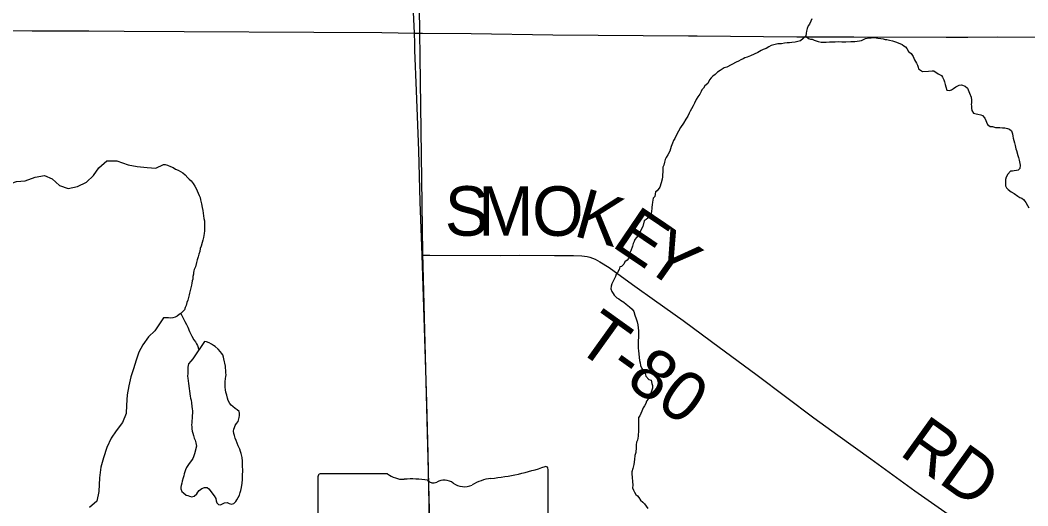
# Model space of a CAD drawing. Extents: x 0 to 34, y 0 to 22.
# Drawn here: x 6.525 to 7.68, y 16.8 to 17.358 of the extents above; entities that cross this region are included whole.
import ezdxf

# ---------------------------------------------------------------- set-up
doc = ezdxf.new("R2010")
doc.units = 0
for name, color, linetype in [('GM_X_County_Road', 7, 'Continuous'), ('GM_X_Minor_Lake', 7, 'Continuous'), ('GM_X_Minor_River', 7, 'Continuous'), ('GM_X_Rail_Line', 7, 'Continuous'), ('GM_X_State_Route', 7, 'Continuous'), ('GM_X_State_Shield', 7, 'Continuous'), ('GM_X_Township_Road', 7, 'Continuous'), ('GM_X_Township_Road_Text', 7, 'Continuous')]:
    doc.layers.add(name, color=color, linetype=linetype)

msp = doc.modelspace()

# ---------------------------------------------------------------- linework, layer by layer
at = {"layer": 'GM_X_County_Road'}
for points in [[(6.1692, 17.3475), (6.2373, 17.3474), (6.3118, 17.3469), (6.3927, 17.3464), (6.5388, 17.3456), (6.604, 17.3453), (6.6444, 17.3451), (6.7129, 17.3447), (6.8618, 17.3438), (6.9395, 17.3434), (6.9768, 17.3429)], [(6.9768, 17.3429), (6.9861, 17.3428), (7.0421, 17.3422), (7.1354, 17.3407), (7.2908, 17.3398), (7.3009, 17.3397)], [(7.3009, 17.3397), (7.4151, 17.3387), (7.4804, 17.3384), (7.586, 17.338), (7.6111, 17.3382)], [(7.6111, 17.3382), (7.6451, 17.3384), (7.7944, 17.3378), (7.8503, 17.3373), (7.8877, 17.3371), (7.9343, 17.3368), (8.0462, 17.3362), (8.1332, 17.3351), (8.163, 17.335)]]:
    msp.add_lwpolyline(points, dxfattribs=at)
at = {"layer": 'GM_X_Minor_Lake'}
for points in [[(6.7365, 16.9889), (6.723, 16.969), (6.7208, 16.9663), (6.7181, 16.9633), (6.7174, 16.9594), (6.7171, 16.9568), (6.7171, 16.9545), (6.7171, 16.9522), (6.7168, 16.9492), (6.7172, 16.9469), (6.7176, 16.9438), (6.718, 16.9408), (6.7201, 16.9263)], [(6.7714, 16.8782), (6.7707, 16.8812), (6.7699, 16.8835), (6.7695, 16.8862), (6.7698, 16.8885), (6.7706, 16.8904), (6.7717, 16.8927), (6.7732, 16.895), (6.7751, 16.8973), (6.7761, 16.9018), (6.7765, 16.9041), (6.7765, 16.9068), (6.7761, 16.9087), (6.7738, 16.9106), (6.7715, 16.9121), (6.7688, 16.9143), (6.7669, 16.9158), (6.7653, 16.9177), (6.7634, 16.9215), (6.7626, 16.9241), (6.7618, 16.9276), (6.761, 16.931), (6.7606, 16.9336), (6.7602, 16.9367), (6.7602, 16.9386), (6.7602, 16.9409), (6.7602, 16.9428), (6.7605, 16.9466), (6.7608, 16.9489), (6.7612, 16.9508), (6.7608, 16.953), (6.7608, 16.9561), (6.7604, 16.9584), (6.7604, 16.9607), (6.7584, 16.969), (6.758, 16.9709), (6.7572, 16.9736), (6.756, 16.9755), (6.7549, 16.9773), (6.7522, 16.9804), (6.7487, 16.9834), (6.7468, 16.9845), (6.7445, 16.986), (6.7418, 16.9875), (6.7388, 16.9886), (6.7365, 16.9889)], [(6.7201, 16.9263), (6.7204, 16.9241), (6.7212, 16.9218), (6.7216, 16.9188), (6.722, 16.9146), (6.7224, 16.9119), (6.7225, 16.9093), (6.7225, 16.9066), (6.7221, 16.9043), (6.7222, 16.9013), (6.7218, 16.8978), (6.7219, 16.8956), (6.7215, 16.8933), (6.7219, 16.891), (6.7219, 16.8887), (6.7223, 16.8861), (6.7231, 16.8838), (6.7239, 16.8811), (6.7247, 16.8781), (6.7258, 16.8758), (6.7266, 16.8728), (6.727, 16.8709), (6.7271, 16.869), (6.7249, 16.8602), (6.7238, 16.8568), (6.723, 16.8549), (6.7215, 16.8526), (6.7189, 16.8491), (6.7174, 16.8468), (6.7159, 16.8445), (6.7148, 16.8418), (6.7137, 16.8395), (6.7129, 16.8372), (6.7126, 16.835), (6.7118, 16.8327), (6.7107, 16.8289), (6.7104, 16.8266), (6.7096, 16.8239), (6.7093, 16.822), (6.7093, 16.8201), (6.7105, 16.8171), (6.7124, 16.8152), (6.7155, 16.8129), (6.7174, 16.8122), (6.7193, 16.8114), (6.7219, 16.8107), (6.7246, 16.8115), (6.7276, 16.8142), (6.7287, 16.8161), (6.7302, 16.818), (6.7332, 16.8203), (6.7363, 16.8215), (6.7393, 16.8215), (6.7412, 16.82), (6.7474, 16.8121), (6.7493, 16.8087), (6.7497, 16.8064), (6.7505, 16.8038), (6.7524, 16.8019), (6.7547, 16.8015), (6.757, 16.8027), (6.7593, 16.8039), (6.7623, 16.8043), (6.7646, 16.8032), (6.7673, 16.8024), (6.7699, 16.8032), (6.7722, 16.8055), (6.7733, 16.8074), (6.7748, 16.8101), (6.7763, 16.8128), (6.7774, 16.8158), (6.7781, 16.8181), (6.7789, 16.8216), (6.7796, 16.8265), (6.7799, 16.8307), (6.7799, 16.8353), (6.7802, 16.841), (6.7801, 16.8463), (6.7801, 16.8516), (6.7797, 16.8558), (6.7785, 16.8604), (6.7777, 16.863), (6.7769, 16.8653), (6.7757, 16.8676), (6.7749, 16.8695), (6.7726, 16.8755), (6.7714, 16.8782)]]:
    msp.add_lwpolyline(points, dxfattribs=at)
at = {"layer": 'GM_X_Minor_River'}
for points in [[(7.4322, 17.3593), (7.4311, 17.3566), (7.4296, 17.3531), (7.4281, 17.3512), (7.427, 17.3482), (7.4263, 17.3451), (7.4256, 17.3428), (7.4252, 17.3394), (7.4192, 17.334), (7.4131, 17.3324), (7.4093, 17.332), (7.4067, 17.3316), (7.404, 17.3316), (7.401, 17.3312), (7.3976, 17.3307), (7.3934, 17.3307), (7.3888, 17.3295), (7.3858, 17.3287), (7.3831, 17.3272), (7.3801, 17.3252), (7.3763, 17.324), (7.3741, 17.3229), (7.3703, 17.3206), (7.3661, 17.3186), (7.362, 17.3167), (7.3582, 17.3151), (7.3555, 17.3143), (7.3536, 17.3132), (7.351, 17.312), (7.3483, 17.3108), (7.3457, 17.3093), (7.3347, 17.3038), (7.3317, 17.303), (7.3294, 17.3015), (7.3272, 17.2999), (7.3241, 17.298), (7.3215, 17.2953), (7.3189, 17.2934), (7.317, 17.2915), (7.3151, 17.2892), (7.3129, 17.285), (7.3098, 17.2823), (7.308, 17.2796), (7.3061, 17.2776), (7.3054, 17.2757), (7.3039, 17.2727), (7.3016, 17.2696), (7.2997, 17.2665), (7.2979, 17.2623), (7.2964, 17.2593), (7.2945, 17.2558), (7.2927, 17.2532), (7.2915, 17.2509), (7.29, 17.2474), (7.2878, 17.244), (7.2852, 17.2394), (7.2818, 17.2344), (7.2796, 17.2302), (7.2773, 17.226), (7.2751, 17.2221), (7.2736, 17.2195), (7.2725, 17.2164), (7.271, 17.2126), (7.2695, 17.2072), (7.2673, 17.203), (7.2654, 17.2), (7.2643, 17.1977), (7.2636, 17.1946), (7.2625, 17.1912), (7.2617, 17.1889), (7.2614, 17.1866), (7.2614, 17.1832), (7.2611, 17.1805), (7.2611, 17.1779), (7.2607, 17.1752), (7.2596, 17.171), (7.2582, 17.166), (7.2552, 17.1618), (7.2533, 17.1607), (7.2522, 17.1553), (7.2503, 17.1534), (7.2496, 17.1488), (7.2493, 17.1458), (7.2489, 17.1431), (7.2489, 17.1412), (7.2486, 17.1389), (7.2482, 17.1351), (7.2464, 17.132), (7.2426, 17.129), (7.2403, 17.1274), (7.2385, 17.1209), (7.2362, 17.1167)], [(7.4252, 17.3394), (7.4283, 17.3368), (7.4306, 17.336), (7.4325, 17.3357), (7.4348, 17.3346), (7.4393, 17.3331), (7.4428, 17.3324), (7.4451, 17.3324), (7.4485, 17.3324), (7.4523, 17.3328), (7.4553, 17.3329), (7.4591, 17.3329), (7.4629, 17.3333), (7.4667, 17.333), (7.4713, 17.333), (7.477, 17.3331), (7.4815, 17.3331), (7.4842, 17.3336), (7.4869, 17.334), (7.4891, 17.3344), (7.4937, 17.3367), (7.4978, 17.3375), (7.5001, 17.3375), (7.5035, 17.3376), (7.5077, 17.3372), (7.5112, 17.3365), (7.5138, 17.3361), (7.5161, 17.3354), (7.518, 17.3354), (7.5214, 17.3347), (7.5245, 17.334), (7.5268, 17.3332), (7.5291, 17.3325), (7.5356, 17.3299), (7.5375, 17.3284), (7.5394, 17.3269), (7.5409, 17.325), (7.5429, 17.3216), (7.5459, 17.3194), (7.5482, 17.316), (7.5498, 17.3122), (7.5521, 17.3084), (7.5533, 17.3061), (7.5541, 17.3038), (7.5545, 17.3019), (7.5591, 17.2986), (7.5659, 17.299), (7.5701, 17.2994), (7.572, 17.2995), (7.5769, 17.2961), (7.5808, 17.2942), (7.5819, 17.2923), (7.5835, 17.2893), (7.5843, 17.287), (7.5851, 17.284), (7.5858, 17.281), (7.587, 17.2775), (7.5901, 17.2768), (7.5923, 17.2776), (7.5946, 17.2791), (7.5972, 17.2811), (7.601, 17.283), (7.6037, 17.2834), (7.6079, 17.282), (7.6106, 17.2797), (7.6129, 17.274), (7.6148, 17.2695), (7.6153, 17.2657), (7.6153, 17.263), (7.6149, 17.2611), (7.615, 17.2592), (7.615, 17.2569), (7.6154, 17.2539), (7.6173, 17.2508), (7.6204, 17.2501), (7.6226, 17.2498), (7.6257, 17.249), (7.6276, 17.2483), (7.6303, 17.2453), (7.6334, 17.2381), (7.6365, 17.2358), (7.6391, 17.2355), (7.6426, 17.2347), (7.6452, 17.2344), (7.6475, 17.2344), (7.6506, 17.2341), (7.6532, 17.2341), (7.6563, 17.2334), (7.6586, 17.2326), (7.6609, 17.2308), (7.662, 17.2273), (7.6624, 17.2247), (7.6628, 17.2224), (7.6636, 17.2197), (7.6644, 17.2171), (7.6652, 17.2137), (7.666, 17.2099), (7.6668, 17.208), (7.6684, 17.2023), (7.6691, 17.2), (7.6696, 17.197)], [(6.4874, 17.1877), (6.4887, 17.1752), (6.4964, 17.1688), (6.5093, 17.1685), (6.521, 17.1727), (6.5309, 17.1732), (6.5423, 17.1774), (6.5529, 17.1794), (6.5617, 17.1757), (6.5701, 17.1681), (6.58, 17.1644), (6.591, 17.1667), (6.6012, 17.1717), (6.6091, 17.1794), (6.6155, 17.1882), (6.6246, 17.1962), (6.636, 17.1963), (6.6489, 17.1918), (6.6592, 17.1896), (6.6706, 17.1885), (6.6805, 17.1878), (6.6894, 17.1921)], [(6.6894, 17.1921), (6.6915, 17.1921), (6.6938, 17.1913), (6.6976, 17.1898), (6.7003, 17.1887), (6.703, 17.1869), (6.7064, 17.1854), (6.7087, 17.1839), (6.7114, 17.1824), (6.7144, 17.1801), (6.7171, 17.1767), (6.719, 17.1752), (6.721, 17.1733), (6.7233, 17.1703), (6.7252, 17.1673), (6.7268, 17.1646), (6.7303, 17.1567), (6.7314, 17.1544), (6.7318, 17.1514), (6.733, 17.1468), (6.7338, 17.1427), (6.7346, 17.1392), (6.735, 17.1362), (6.7354, 17.1332), (6.7358, 17.1301), (6.7363, 17.1275), (6.7363, 17.1248), (6.7363, 17.1218), (6.7363, 17.1191), (6.7364, 17.116), (6.736, 17.113), (6.7353, 17.1084), (6.7346, 17.1054), (6.7338, 17.1027), (6.7324, 17.0985), (6.7316, 17.0958), (6.7309, 17.0924), (6.7298, 17.0893), (6.7291, 17.0863), (6.728, 17.0828), (6.7272, 17.0798), (6.7261, 17.0748), (6.7246, 17.0718), (6.7243, 17.0699), (6.7239, 17.068), (6.7236, 17.0661), (6.7232, 17.0634), (6.7229, 17.0607), (6.7221, 17.0588), (6.7218, 17.0561), (6.7214, 17.0535), (6.7207, 17.0504), (6.7199, 17.0474), (6.7192, 17.0443), (6.7189, 17.0424), (6.7181, 17.0394), (6.7174, 17.0363), (6.7163, 17.0336), (6.7152, 17.0302), (6.7144, 17.0279), (6.7133, 17.0252), (6.7111, 17.0229), (6.7092, 17.021), (6.7073, 17.0198), (6.705, 17.0179), (6.7028, 17.0168), (6.7001, 17.016), (6.6975, 17.0156), (6.6952, 17.0163), (6.6914, 17.0163), (6.6894, 17.0162), (6.6894, 17.0162), (6.6898, 17.0162)], [(7.6696, 17.197), (7.67, 17.1951), (7.6704, 17.1932), (7.6708, 17.1913), (7.6704, 17.1875), (7.6685, 17.1855), (7.6666, 17.1851), (7.664, 17.1847), (7.6621, 17.1843), (7.6598, 17.1843), (7.6568, 17.1809), (7.6549, 17.1774), (7.6542, 17.1747), (7.6542, 17.1725), (7.6542, 17.1698), (7.6543, 17.1675), (7.6554, 17.1652), (7.6573, 17.1634), (7.6608, 17.1607), (7.6639, 17.1589), (7.6681, 17.1559), (7.6707, 17.1544), (7.6727, 17.1536), (7.6746, 17.1521), (7.6761, 17.1502), (7.6776, 17.1484), (7.6792, 17.1449), (7.6807, 17.1423)], [(7.2362, 17.1167), (7.234, 17.1117), (7.2314, 17.1083), (7.2295, 17.106), (7.2288, 17.1037), (7.2277, 17.1014), (7.2269, 17.0984), (7.2247, 17.093), (7.2236, 17.0907), (7.2229, 17.0869), (7.2221, 17.0842), (7.2206, 17.0823), (7.218, 17.0804), (7.2169, 17.0777), (7.2142, 17.075), (7.2123, 17.0746), (7.2116, 17.0716), (7.2097, 17.0681), (7.2079, 17.0662), (7.2071, 17.0635), (7.2056, 17.0605), (7.2041, 17.0574), (7.203, 17.0551), (7.2023, 17.0524), (7.2019, 17.0494), (7.2031, 17.0463), (7.2047, 17.0441), (7.2058, 17.0422), (7.2089, 17.0392), (7.2112, 17.0381), (7.2131, 17.0366), (7.215, 17.0354), (7.2169, 17.0343), (7.2196, 17.0317), (7.2234, 17.0287), (7.2265, 17.026), (7.2284, 17.0234), (7.2296, 17.0192), (7.2308, 17.0151), (7.232, 17.0116), (7.2328, 17.0082), (7.2332, 17.0048), (7.2336, 17.0014), (7.2336, 16.998), (7.2337, 16.9957), (7.2337, 16.9934), (7.2333, 16.9907), (7.2333, 16.9884), (7.2334, 16.9843), (7.2334, 16.9812), (7.2338, 16.9782), (7.2339, 16.9747), (7.2343, 16.9706), (7.2347, 16.9671), (7.2355, 16.9645), (7.2359, 16.9615), (7.2375, 16.958), (7.2413, 16.9524), (7.2421, 16.9493), (7.2456, 16.9456), (7.2482, 16.9445), (7.249, 16.941), (7.2498, 16.9384), (7.2498, 16.9353), (7.2484, 16.9319), (7.2469, 16.9273), (7.2446, 16.9227), (7.2428, 16.9204), (7.242, 16.9178), (7.2405, 16.9151), (7.239, 16.9128), (7.2376, 16.909), (7.2353, 16.9036), (7.2338, 16.9017), (7.2335, 16.8967), (7.2335, 16.8937), (7.2336, 16.8903), (7.2336, 16.8849), (7.2333, 16.8827), (7.2333, 16.8804), (7.2326, 16.8758), (7.2315, 16.8735), (7.2311, 16.8705), (7.2308, 16.8674), (7.2304, 16.8617), (7.2293, 16.8583), (7.229, 16.8537), (7.2283, 16.848), (7.2272, 16.8434), (7.2261, 16.8396), (7.2261, 16.8373), (7.227, 16.824), (7.2267, 16.8213), (7.2278, 16.8183), (7.229, 16.816), (7.2305, 16.8134), (7.2325, 16.8119), (7.234, 16.81), (7.2359, 16.807), (7.2386, 16.8047), (7.2405, 16.8028)], [(6.7093, 17.0211), (6.7138, 17.0119), (6.7158, 17.0085), (6.7173, 17.0055), (6.7193, 17.0006), (6.722, 16.9953), (6.7243, 16.9911), (6.7259, 16.9888), (6.7274, 16.9862), (6.7282, 16.9843), (6.73, 16.9793)], [(6.6894, 17.0162), (6.6795, 17.0011), (6.6723, 16.9942), (6.6659, 16.9851), (6.6611, 16.9767), (6.6581, 16.9675), (6.6551, 16.9576), (6.6521, 16.9485), (6.6496, 16.9382), (6.6477, 16.9279), (6.6471, 16.9158), (6.6467, 16.9063), (6.6426, 16.896), (6.6351, 16.8864), (6.6295, 16.878), (6.6246, 16.8673), (6.6205, 16.8555), (6.6175, 16.8449), (6.6161, 16.8327), (6.6154, 16.8171), (6.6129, 16.806), (6.6046, 16.7984)], [(7.2405, 16.8028), (7.2444, 16.7975)]]:
    msp.add_lwpolyline(points, dxfattribs=at)
at = {"layer": 'GM_X_Rail_Line'}
msp.add_lwpolyline([(7.0001, 16.5307), (6.9984, 16.6334), (6.9864, 17.0905), (6.98, 17.5697), (6.9695, 17.6243), (6.954, 17.6886), (6.9362, 17.7597), (6.9253, 17.8041)], dxfattribs=at)
at = {"layer": 'GM_X_State_Route'}
for points in [[(6.9773, 17.3311), (6.9768, 17.3429), (6.9759, 17.3667), (6.9756, 17.3916), (6.9758, 17.4133), (6.9768, 17.4356)], [(6.994, 16.7825), (6.9927, 16.8602), (6.9913, 16.9192), (6.9897, 16.9689), (6.9856, 17.088), (6.9835, 17.1492), (6.9818, 17.2082), (6.9793, 17.2766), (6.9775, 17.3232), (6.9773, 17.3311)]]:
    msp.add_lwpolyline(points, dxfattribs=at)
at = {"layer": 'GM_X_State_Shield'}
for p, q in [((6.8663, 16.8338), (6.8663, 16.6337)), ((6.9461, 16.8372), (6.8689, 16.8372)), ((7.13, 16.7375), (7.13, 16.8422))]:
    msp.add_line(p, q, dxfattribs=at)
for centre, radius, start, end in [((7.0361, 17.1101), 0.2796, 275.8445, 288.9065), ((7.1271, 16.8426), 0.00294, 351.8621, 97.738), ((6.8694, 16.8342), 0.00305, 98.1301, 188.1301), ((6.9645, 16.8605), 0.0296, 231.6195, 271.1119), ((6.9744, 16.7249), 0.1064, 80.4867, 94.9883), ((6.9985, 16.8353), 0.00855, 219.7921, 297.1024), ((7.0111, 16.8121), 0.0178, 54.4667, 119.1411), ((7.034, 16.8438), 0.0214, 233.8562, 294.8282), ((7.0717, 16.7761), 0.0563, 97.3462, 120.7689)]:
    msp.add_arc(centre, radius, start, end, dxfattribs=at)
at = {"layer": 'GM_X_Township_Road'}
msp.add_lwpolyline([(6.9856, 17.088), (6.9945, 17.088), (7.0753, 17.0877), (7.0971, 17.0879), (7.1375, 17.0878), (7.1593, 17.0877), (7.1687, 17.0873), (7.1718, 17.0869), (7.1749, 17.0864), (7.178, 17.0857), (7.1811, 17.0847), (7.184, 17.0834), (7.1895, 17.0804), (7.1999, 17.0738), (7.21, 17.0665), (7.2295, 17.0525), (7.2518, 17.0365), (7.2847, 17.013), (7.3173, 16.9891), (7.3697, 16.9502), (7.4344, 16.9016), (7.4621, 16.8817), (7.5, 16.8544), (7.5501, 16.8177), (7.6239, 16.7659)], dxfattribs=at)

# ---------------------------------------------------------------- texts
at = {"layer": 'GM_X_Township_Road_Text'}
for s, height, rotation, p in [('S', 0.0568, 0, (7.0117, 17.1104)), ('M', 0.0568, 359.9985, (7.05, 17.1104)), ('O', 0.0568, 359.7322, (7.1116, 17.1104)), ('K', 0.0568, 344.3025, (7.1576, 17.1107)), ('E', 0.0568, 325.9195, (7.2014, 17.0992)), ('Y', 0.0568, 324.7973, (7.2363, 17.0756)), ('T-80', 0.05682, 324.3811, (7.1591, 16.9821)), ('RD', 0.05682, 324.4064, (7.5311, 16.86))]:
    msp.add_text(s, height=height, rotation=rotation, dxfattribs=at).set_placement(p)

doc.saveas('drawing.dxf')
